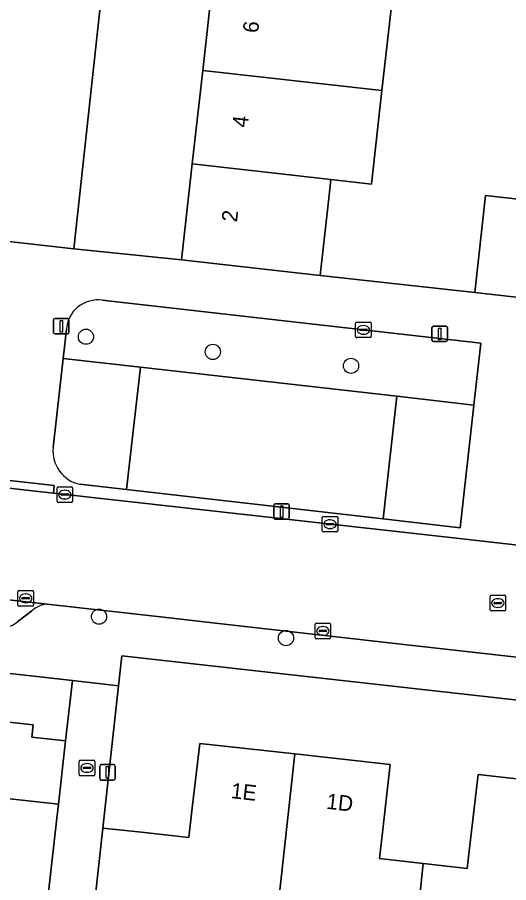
# Model space of a CAD drawing. Extents: x 162082 to 163401, y 388089 to 388636.
# Drawn here: x 162878.5 to 162910.1, y 388312.7 to 388368.3 of the extents above; entities that cross this region are included whole.
import ezdxf

# ---------------------------------------------------------------- set-up
doc = ezdxf.new("R2010")
doc.units = 0
for name, color, linetype in [('IMGEO_Boom', 7, 'Continuous'), ('IMGEO_Erf', 7, 'Continuous'), ('IMGEO_Groenvoorziening', 7, 'Continuous'), ('IMGEO_Kolk', 7, 'Continuous'), ('IMGEO_Lichtmast', 7, 'Continuous'), ('IMGEO_Muur', 7, 'Continuous'), ('IMGEO_Pand', 7, 'Continuous'), ('IMGEO_Pand_nummerreeks', 7, 'Continuous'), ('IMGEO_Parkeervlak_open', 7, 'Continuous'), ('IMGEO_Rijbaan_lokaal_open', 7, 'Continuous'), ('IMGEO_Rioolput', 7, 'Continuous'), ('IMGEO_Voetpad_open', 7, 'Continuous')]:
    doc.layers.add(name, color=color, linetype=linetype)

msp = doc.modelspace()

# ---------------------------------------------------------------- linework, layer by layer
at = {"layer": 'IMGEO_Boom'}
for centre in [(162882.884, 388347.77), (162891.045, 388346.791), (162899.93, 388345.899), (162883.725, 388329.762), (162895.748, 388328.386)]:
    msp.add_circle(centre, 0.489, dxfattribs=at)
at = {"layer": 'IMGEO_Erf'}
for points in [[(162885.887, 388388.094), (162882.103, 388353.418), (162889.026, 388352.708), (162889.717, 388358.88), (162890.391, 388364.901), (162891.065, 388370.923)], [(162902.587, 388369.632), (162901.913, 388363.61), (162901.239, 388357.589), (162898.633, 388357.881), (162898.498, 388356.678), (162897.942, 388351.709), (162907.892, 388350.612), (162908.579, 388356.845), (162912.564, 388356.407), (162914.215, 388369.801)], [(162873.336, 388323.497), (162879.499, 388322.807), (162879.41, 388322.012), (162881.575, 388321.77), (162882.015, 388325.663), (162868.576, 388327.156)], [(162936.982, 388321.452), (162936.117, 388321.549), (162885.195, 388327.249), (162884.982, 388325.32), (162883.969, 388316.16), (162886.447, 388315.894), (162889.495, 388315.567), (162889.697, 388317.27), (162890.211, 388321.615), (162896.323, 388320.93), (162902.442, 388320.245), (162901.945, 388315.874), (162901.754, 388314.199), (162904.571, 388313.878), (162907.407, 388313.555), (162907.599, 388315.242), (162908.096, 388319.615), (162914.202, 388318.92), (162920.322, 388318.223), (162919.824, 388313.864), (162919.63, 388312.164)], [(162879.636, 388304.63), (162881.014, 388316.806), (162881.114, 388317.7), (162876.019, 388318.271)]]:
    msp.add_lwpolyline(points, dxfattribs=at)
at = {"layer": 'IMGEO_Groenvoorziening'}
for points in [[(162881.633, 388348.237), (162881.421, 388346.373), (162886.389, 388345.809), (162902.866, 388343.939), (162907.834, 388343.376), (162908.277, 388347.351), (162883.932, 388350.114)], [(162882.497, 388338.28), (162885.495, 388337.937), (162886.389, 388345.809), (162881.421, 388346.373), (162880.77, 388340.639)]]:
    msp.add_lwpolyline(points, dxfattribs=at)
for points in [[(162885.495, 388337.937), (162901.986, 388336.052), (162902.866, 388343.939), (162886.389, 388345.809)], [(162901.986, 388336.052), (162906.954, 388335.484), (162907.834, 388343.376), (162902.866, 388343.939)]]:
    msp.add_lwpolyline(points, close=True, dxfattribs=at)
for centre, radius, start, end in [((162883.635, 388348.131), 2.005, 81.4898, 176.9695), ((162882.955, 388340.427), 2.196, 174.4672, 257.9477)]:
    msp.add_arc(centre, radius, start, end, dxfattribs=at)
at = {"layer": 'IMGEO_Kolk'}
for p, q in [((162900.225, 388347.783), (162900.225, 388348.635)), ((162900.3, 388348.709), (162901.152, 388348.709)), ((162901.226, 388348.635), (162901.226, 388347.783)), ((162900.484, 388348.203), (162900.484, 388348.215)), ((162900.922, 388348.166), (162900.524, 388348.166)), ((162900.527, 388348.252), (162900.925, 388348.252)), ((162900.713, 388348.489), (162900.738, 388348.489)), ((162900.968, 388348.215), (162900.968, 388348.203)), ((162901.152, 388347.709), (162900.3, 388347.709)), ((162900.736, 388347.929), (162900.711, 388347.929)), ((162881.023, 388337.188), (162881.023, 388338.04)), ((162881.098, 388338.114), (162881.95, 388338.114)), ((162882.024, 388338.04), (162882.024, 388337.188)), ((162881.282, 388337.608), (162881.282, 388337.62)), ((162881.72, 388337.571), (162881.322, 388337.571)), ((162881.325, 388337.657), (162881.723, 388337.657)), ((162881.511, 388337.894), (162881.536, 388337.894)), ((162881.766, 388337.62), (162881.766, 388337.608)), ((162881.95, 388337.114), (162881.098, 388337.114)), ((162881.534, 388337.334), (162881.509, 388337.334)), ((162898.08, 388335.285), (162898.08, 388336.137)), ((162898.155, 388336.211), (162899.007, 388336.211)), ((162898.568, 388335.991), (162898.593, 388335.991)), ((162899.081, 388336.137), (162899.081, 388335.285)), ((162898.339, 388335.705), (162898.339, 388335.717)), ((162898.777, 388335.668), (162898.379, 388335.668)), ((162898.382, 388335.754), (162898.78, 388335.754)), ((162898.591, 388335.431), (162898.566, 388335.431)), ((162898.823, 388335.717), (162898.823, 388335.705)), ((162899.007, 388335.211), (162898.155, 388335.211)), ((162878.511, 388330.519), (162878.511, 388331.371)), ((162878.586, 388331.445), (162879.438, 388331.445)), ((162879.512, 388331.371), (162879.512, 388330.519)), ((162878.77, 388330.939), (162878.77, 388330.951)), ((162879.208, 388330.902), (162878.81, 388330.902)), ((162878.813, 388330.988), (162879.211, 388330.988)), ((162878.999, 388331.225), (162879.024, 388331.225)), ((162879.254, 388330.951), (162879.254, 388330.939)), ((162879.438, 388330.445), (162878.586, 388330.445)), ((162879.022, 388330.665), (162878.997, 388330.665)), ((162897.616, 388328.421), (162897.616, 388329.273)), ((162897.691, 388329.347), (162898.543, 388329.347)), ((162898.617, 388329.273), (162898.617, 388328.421)), ((162897.875, 388328.841), (162897.875, 388328.853)), ((162898.313, 388328.804), (162897.915, 388328.804)), ((162897.918, 388328.89), (162898.316, 388328.89)), ((162898.104, 388329.127), (162898.129, 388329.127)), ((162898.359, 388328.853), (162898.359, 388328.841)), ((162898.543, 388328.347), (162897.691, 388328.347)), ((162898.127, 388328.567), (162898.102, 388328.567)), ((162882.451, 388319.605), (162882.451, 388320.457)), ((162882.526, 388320.531), (162883.378, 388320.531)), ((162882.939, 388320.311), (162882.964, 388320.311)), ((162883.452, 388320.457), (162883.452, 388319.605)), ((162882.71, 388320.025), (162882.71, 388320.037)), ((162883.148, 388319.988), (162882.75, 388319.988)), ((162882.753, 388320.074), (162883.151, 388320.074)), ((162882.962, 388319.751), (162882.937, 388319.751)), ((162883.194, 388320.037), (162883.194, 388320.025)), ((162883.378, 388319.531), (162882.526, 388319.531))]:
    msp.add_line(p, q, dxfattribs=at)
for points in [[(162900.225, 388347.783), (162900.225, 388348.635)], [(162900.3, 388348.709), (162901.152, 388348.709)], [(162901.226, 388348.635), (162901.226, 388347.783)], [(162901.152, 388347.709), (162900.3, 388347.709)], [(162881.023, 388337.188), (162881.023, 388338.04)], [(162881.098, 388338.114), (162881.95, 388338.114)], [(162882.024, 388338.04), (162882.024, 388337.188)], [(162881.95, 388337.114), (162881.098, 388337.114)], [(162898.08, 388335.285), (162898.08, 388336.137)], [(162898.155, 388336.211), (162899.007, 388336.211)], [(162899.081, 388336.137), (162899.081, 388335.285)], [(162899.007, 388335.211), (162898.155, 388335.211)], [(162878.511, 388330.519), (162878.511, 388331.371)], [(162878.586, 388331.445), (162879.438, 388331.445)], [(162879.512, 388331.371), (162879.512, 388330.519)], [(162879.438, 388330.445), (162878.586, 388330.445)], [(162897.616, 388328.421), (162897.616, 388329.273)], [(162897.691, 388329.347), (162898.543, 388329.347)], [(162898.617, 388329.273), (162898.617, 388328.421)], [(162898.543, 388328.347), (162897.691, 388328.347)], [(162882.451, 388319.605), (162882.451, 388320.457)], [(162882.526, 388320.531), (162883.378, 388320.531)], [(162883.452, 388320.457), (162883.452, 388319.605)], [(162883.378, 388319.531), (162882.526, 388319.531)]]:
    msp.add_lwpolyline(points, dxfattribs=at)
for centre, radius, start, end in [((162900.302, 388348.633), 0.0765, 91.552, 178.448), ((162900.302, 388348.633), 0.0765, 91.552, 178.448), ((162901.15, 388348.633), 0.0765, 1.552, 88.448), ((162901.15, 388348.633), 0.0765, 1.552, 88.448), ((162900.524, 388348.212), 0.0403, 85.8775, 175.7526), ((162900.521, 388348.202), 0.0366, 178.938, 274.7102), ((162900.925, 388348.209), 0.043, 264.8664, 352.4533), ((162900.929, 388348.214), 0.0386, 1.7309, 96.639), ((162900.302, 388347.785), 0.0765, 181.552, 268.448), ((162900.302, 388347.785), 0.0765, 181.552, 268.448), ((162901.15, 388347.785), 0.0765, 271.552, 358.448), ((162901.15, 388347.785), 0.0765, 271.552, 358.448), ((162881.1, 388338.038), 0.0765, 91.552, 178.448), ((162881.1, 388338.038), 0.0765, 91.552, 178.448), ((162881.948, 388338.038), 0.0765, 1.552, 88.448), ((162881.948, 388338.038), 0.0765, 1.552, 88.448), ((162881.322, 388337.617), 0.0403, 85.8775, 175.7526), ((162881.319, 388337.607), 0.0366, 178.938, 274.7102), ((162881.723, 388337.614), 0.043, 264.8664, 352.4533), ((162881.727, 388337.619), 0.0386, 1.7309, 96.639), ((162881.1, 388337.19), 0.0765, 181.552, 268.448), ((162881.1, 388337.19), 0.0765, 181.552, 268.448), ((162881.948, 388337.19), 0.0765, 271.552, 358.448), ((162881.948, 388337.19), 0.0765, 271.552, 358.448), ((162898.157, 388336.135), 0.0765, 91.552, 178.448), ((162898.157, 388336.135), 0.0765, 91.552, 178.448), ((162899.005, 388336.135), 0.0765, 1.552, 88.448), ((162899.005, 388336.135), 0.0765, 1.552, 88.448), ((162898.157, 388335.287), 0.0765, 181.552, 268.448), ((162898.157, 388335.287), 0.0765, 181.552, 268.448), ((162898.379, 388335.714), 0.0403, 85.8775, 175.7526), ((162898.376, 388335.704), 0.0366, 178.938, 274.7102), ((162898.78, 388335.711), 0.043, 264.8664, 352.4533), ((162898.784, 388335.716), 0.0386, 1.7309, 96.639), ((162899.005, 388335.287), 0.0765, 271.552, 358.448), ((162899.005, 388335.287), 0.0765, 271.552, 358.448), ((162878.588, 388331.369), 0.0765, 91.552, 178.448), ((162878.588, 388331.369), 0.0765, 91.552, 178.448), ((162879.436, 388331.369), 0.0765, 1.552, 88.448), ((162879.436, 388331.369), 0.0765, 1.552, 88.448), ((162878.81, 388330.948), 0.0403, 85.8775, 175.7526), ((162878.807, 388330.938), 0.0366, 178.938, 274.7102), ((162879.211, 388330.945), 0.043, 264.8664, 352.4533), ((162879.215, 388330.95), 0.0386, 1.7309, 96.639), ((162878.588, 388330.521), 0.0765, 181.552, 268.448), ((162878.588, 388330.521), 0.0765, 181.552, 268.448), ((162879.436, 388330.521), 0.0765, 271.552, 358.448), ((162879.436, 388330.521), 0.0765, 271.552, 358.448), ((162897.693, 388329.271), 0.0765, 91.552, 178.448), ((162897.693, 388329.271), 0.0765, 91.552, 178.448), ((162898.541, 388329.271), 0.0765, 1.552, 88.448), ((162898.541, 388329.271), 0.0765, 1.552, 88.448), ((162897.915, 388328.85), 0.0403, 85.8775, 175.7526), ((162897.912, 388328.84), 0.0366, 178.938, 274.7102), ((162898.316, 388328.847), 0.043, 264.8664, 352.4533), ((162898.32, 388328.852), 0.0386, 1.7309, 96.639), ((162897.693, 388328.423), 0.0765, 181.552, 268.448), ((162897.693, 388328.423), 0.0765, 181.552, 268.448), ((162898.541, 388328.423), 0.0765, 271.552, 358.448), ((162898.541, 388328.423), 0.0765, 271.552, 358.448), ((162882.528, 388320.455), 0.0765, 91.552, 178.448), ((162882.528, 388320.455), 0.0765, 91.552, 178.448), ((162883.376, 388320.455), 0.0765, 1.552, 88.448), ((162883.376, 388320.455), 0.0765, 1.552, 88.448), ((162882.75, 388320.034), 0.0403, 85.8775, 175.7526), ((162882.747, 388320.024), 0.0366, 178.938, 274.7102), ((162883.151, 388320.031), 0.043, 264.8664, 352.4533), ((162883.155, 388320.036), 0.0386, 1.7309, 96.639), ((162882.528, 388319.607), 0.0765, 181.552, 268.448), ((162882.528, 388319.607), 0.0765, 181.552, 268.448), ((162883.376, 388319.607), 0.0765, 271.552, 358.448), ((162883.376, 388319.607), 0.0765, 271.552, 358.448)]:
    msp.add_arc(centre, radius, start, end, dxfattribs=at)
for centre, major_axis, ratio, start_param, end_param in [((162900.712, 388348.209), (-0.387, 0.002), 0.722429, 4.712389, 7.853982), ((162900.737, 388348.209), (-0.39, 0.002), 0.717154, 1.570796, 4.712389), ((162881.51, 388337.614), (-0.387, 0.002), 0.722429, 4.712389, 7.853982), ((162881.535, 388337.614), (-0.39, 0.002), 0.717154, 1.570796, 4.712389), ((162898.567, 388335.711), (-0.387, 0.002), 0.722429, 4.712389, 7.853982), ((162898.592, 388335.711), (-0.39, 0.002), 0.717154, 1.570796, 4.712389), ((162878.998, 388330.945), (-0.387, 0.002), 0.722429, 4.712389, 7.853982), ((162879.023, 388330.945), (-0.39, 0.002), 0.717154, 1.570796, 4.712389), ((162898.103, 388328.847), (-0.387, 0.002), 0.722429, 4.712389, 7.853982), ((162898.128, 388328.847), (-0.39, 0.002), 0.717154, 1.570796, 4.712389), ((162882.938, 388320.031), (-0.387, 0.002), 0.722429, 4.712389, 7.853982), ((162882.963, 388320.031), (-0.39, 0.002), 0.717154, 1.570796, 4.712389)]:
    msp.add_ellipse(centre, major_axis=major_axis, ratio=ratio, start_param=start_param, end_param=end_param, dxfattribs=at)
at = {"layer": 'IMGEO_Lichtmast'}
for p, q in [((162880.8, 388348.048), (162880.8, 388348.848)), ((162880.8, 388348.848), (162880.8, 388348.048)), ((162880.9, 388348.948), (162881.69, 388348.948)), ((162881.69, 388348.948), (162880.9, 388348.948)), ((162881.79, 388348.848), (162881.79, 388348.048)), ((162881.79, 388348.048), (162881.79, 388348.848)), ((162905.134, 388347.555), (162905.134, 388348.355)), ((162905.134, 388348.355), (162905.134, 388347.555)), ((162905.234, 388348.455), (162906.024, 388348.455)), ((162906.024, 388348.455), (162905.234, 388348.455)), ((162906.124, 388348.355), (162906.124, 388347.555)), ((162906.124, 388347.555), (162906.124, 388348.355)), ((162881.69, 388347.948), (162880.9, 388347.948)), ((162880.9, 388347.948), (162881.69, 388347.948)), ((162906.024, 388347.455), (162905.234, 388347.455)), ((162905.234, 388347.455), (162906.024, 388347.455)), ((162894.968, 388336.126), (162894.968, 388336.926)), ((162894.968, 388336.926), (162894.968, 388336.126)), ((162895.068, 388337.026), (162895.858, 388337.026)), ((162895.858, 388337.026), (162895.068, 388337.026)), ((162895.958, 388336.926), (162895.958, 388336.126)), ((162895.958, 388336.126), (162895.958, 388336.926)), ((162895.858, 388336.026), (162895.068, 388336.026)), ((162895.068, 388336.026), (162895.858, 388336.026)), ((162883.872, 388320.256), (162884.662, 388320.256)), ((162884.662, 388320.256), (162883.872, 388320.256)), ((162883.772, 388319.356), (162883.772, 388320.156)), ((162883.772, 388320.156), (162883.772, 388319.356)), ((162884.762, 388320.156), (162884.762, 388319.356)), ((162884.762, 388319.356), (162884.762, 388320.156)), ((162884.662, 388319.256), (162883.872, 388319.256)), ((162883.872, 388319.256), (162884.662, 388319.256))]:
    msp.add_line(p, q, dxfattribs=at)
for points in [[(162881.22, 388348.823), (162881.37, 388348.823), (162881.37, 388348.073), (162881.22, 388348.073), (162881.22, 388348.823)], [(162905.554, 388348.33), (162905.704, 388348.33), (162905.704, 388347.58), (162905.554, 388347.58), (162905.554, 388348.33)], [(162895.388, 388336.901), (162895.538, 388336.901), (162895.538, 388336.151), (162895.388, 388336.151), (162895.388, 388336.901)], [(162884.192, 388320.131), (162884.342, 388320.131), (162884.342, 388319.381), (162884.192, 388319.381), (162884.192, 388320.131)]]:
    msp.add_lwpolyline(points, dxfattribs=at)
for centre, start, end in [((162880.9, 388348.848), 90, 180), ((162880.9, 388348.848), 90, 180), ((162881.69, 388348.848), 0, 90), ((162881.69, 388348.848), 360, 90), ((162905.234, 388348.355), 90, 180), ((162905.234, 388348.355), 90, 180), ((162906.024, 388348.355), 0, 90), ((162906.024, 388348.355), 360, 90), ((162880.9, 388348.048), 180, 270), ((162880.9, 388348.048), 180, 270), ((162881.69, 388348.048), 270, 0), ((162881.69, 388348.048), 270, 0), ((162905.234, 388347.555), 180, 270), ((162905.234, 388347.555), 180, 270), ((162906.024, 388347.555), 270, 0), ((162906.024, 388347.555), 270, 0), ((162895.068, 388336.926), 90, 180), ((162895.068, 388336.926), 90, 180), ((162895.858, 388336.926), 0, 90), ((162895.858, 388336.926), 360, 90), ((162895.068, 388336.126), 180, 270), ((162895.068, 388336.126), 180, 270), ((162895.858, 388336.126), 270, 0), ((162895.858, 388336.126), 270, 0), ((162883.872, 388320.156), 90, 180), ((162883.872, 388320.156), 90, 180), ((162884.662, 388320.156), 0, 90), ((162884.662, 388320.156), 360, 90), ((162883.872, 388319.356), 180, 270), ((162883.872, 388319.356), 180, 270), ((162884.662, 388319.356), 270, 0), ((162884.662, 388319.356), 270, 0)]:
    msp.add_arc(centre, 0.1, start, end, dxfattribs=at)
at = {"layer": 'IMGEO_Muur'}
for points in [[(162907.892, 388350.612), (162897.942, 388351.709)], [(162881.014, 388316.806), (162879.636, 388304.63)]]:
    msp.add_lwpolyline(points, dxfattribs=at)
at = {"layer": 'IMGEO_Pand'}
for points in [[(162890.391, 388364.901), (162901.913, 388363.61), (162902.587, 388369.632), (162899.981, 388369.924), (162891.065, 388370.923)], [(162890.391, 388364.901), (162889.717, 388358.88), (162898.633, 388357.881), (162901.239, 388357.589), (162901.913, 388363.61)], [(162898.633, 388357.881), (162889.717, 388358.88), (162889.026, 388352.708), (162897.942, 388351.709), (162898.498, 388356.678)], [(162911.877, 388350.172), (162912.564, 388356.407), (162908.579, 388356.845), (162907.892, 388350.612)], [(162869.223, 388313.359), (162875.392, 388312.668), (162876.019, 388318.271), (162881.114, 388317.7), (162881.575, 388321.77), (162879.41, 388322.012), (162879.499, 388322.807), (162873.336, 388323.497), (162872.805, 388318.759), (162869.868, 388319.088)], [(162894.755, 388306.71), (162896.323, 388320.93), (162890.211, 388321.615), (162889.697, 388317.27), (162889.495, 388315.567), (162886.447, 388315.894), (162883.969, 388316.16), (162883.192, 388309.144), (162882.593, 388303.237), (162885.723, 388302.89), (162888.007, 388306.445), (162891.46, 388306.061), (162891.576, 388307.063)], [(162904.571, 388313.878), (162901.754, 388314.199), (162901.945, 388315.874), (162902.442, 388320.245), (162896.323, 388320.93), (162894.755, 388306.71), (162898.257, 388306.321), (162898.368, 388307.41), (162903.836, 388306.803)], [(162904.571, 388313.878), (162903.836, 388306.803), (162909.255, 388306.202), (162909.677, 388310.134), (162913.18, 388309.749), (162914.202, 388318.92), (162908.096, 388319.615), (162907.599, 388315.242), (162907.407, 388313.555)]]:
    msp.add_lwpolyline(points, close=True, dxfattribs=at)
at = {"layer": 'IMGEO_Parkeervlak_open'}
for points in [[(162880.401, 388330.569), (162802.146, 388339.314)], [(162878.507, 388329.455), (162879.411, 388330.141)]]:
    msp.add_lwpolyline(points, dxfattribs=at)
for centre, radius, start, end in [((162880.483, 388329.02), 1.551, 93.0334, 133.7265), ((162877.295, 388330.889), 1.878, 259.474, 310.2053)]:
    msp.add_arc(centre, radius, start, end, dxfattribs=at)
at = {"layer": 'IMGEO_Rijbaan_lokaal_open'}
msp.add_lwpolyline([(162888.58, 388412.169), (162879.563, 388413.177), (162873.15, 388354.422), (162882.103, 388353.418), (162885.887, 388388.094), (162886.264, 388391.474)], close=True, dxfattribs=at)
msp.add_lwpolyline([(162802.146, 388339.314), (162880.401, 388330.569), (162887.687, 388329.747), (162891.415, 388329.326), (162902.379, 388328.088), (162909.812, 388327.25), (162920.38, 388326.057), (162927.727, 388325.228), (162937.375, 388324.139), (162937.647, 388331.155), (162910.107, 388334.435), (162906.331, 388334.857), (162880.788, 388337.712), (162871.19, 388338.785)], dxfattribs=at)
at = {"layer": 'IMGEO_Rioolput'}
for p, q in [((162908.872, 388330.213), (162908.872, 388331.065)), ((162908.947, 388331.139), (162909.799, 388331.139)), ((162909.36, 388330.919), (162909.385, 388330.919)), ((162909.873, 388331.065), (162909.873, 388330.213)), ((162909.131, 388330.633), (162909.131, 388330.645)), ((162909.569, 388330.596), (162909.171, 388330.596)), ((162909.174, 388330.682), (162909.572, 388330.682)), ((162909.383, 388330.359), (162909.358, 388330.359)), ((162909.615, 388330.645), (162909.615, 388330.633)), ((162909.799, 388330.139), (162908.947, 388330.139))]:
    msp.add_line(p, q, dxfattribs=at)
for points in [[(162908.872, 388330.213), (162908.872, 388331.065)], [(162908.947, 388331.139), (162909.799, 388331.139)], [(162909.873, 388331.065), (162909.873, 388330.213)], [(162909.799, 388330.139), (162908.947, 388330.139)]]:
    msp.add_lwpolyline(points, dxfattribs=at)
for centre, radius, start, end in [((162908.949, 388331.063), 0.0765, 91.552, 178.448), ((162908.949, 388331.063), 0.0765, 91.552, 178.448), ((162909.797, 388331.063), 0.0765, 1.552, 88.448), ((162909.797, 388331.063), 0.0765, 1.552, 88.448), ((162909.171, 388330.642), 0.0403, 85.8775, 175.7526), ((162909.168, 388330.632), 0.0366, 178.938, 274.7102), ((162909.572, 388330.639), 0.043, 264.8664, 352.4533), ((162909.576, 388330.644), 0.0386, 1.7309, 96.639), ((162908.949, 388330.215), 0.0765, 181.552, 268.448), ((162908.949, 388330.215), 0.0765, 181.552, 268.448), ((162909.797, 388330.215), 0.0765, 271.552, 358.448), ((162909.797, 388330.215), 0.0765, 271.552, 358.448)]:
    msp.add_arc(centre, radius, start, end, dxfattribs=at)
for centre, major_axis, ratio, start_param, end_param in [((162909.359, 388330.639), (-0.387, 0.002), 0.722429, 4.712389, 7.853982), ((162909.384, 388330.639), (-0.39, 0.002), 0.717154, 1.570796, 4.712389)]:
    msp.add_ellipse(centre, major_axis=major_axis, ratio=ratio, start_param=start_param, end_param=end_param, dxfattribs=at)
at = {"layer": 'IMGEO_Voetpad_open'}
for points in [[(162938.677, 388341.882), (162939.248, 388347.057), (162936.278, 388347.432), (162927.507, 388348.418), (162924.961, 388348.704), (162915.931, 388349.732), (162913.387, 388350.012), (162911.877, 388350.172), (162907.892, 388350.612), (162897.942, 388351.709), (162889.026, 388352.708), (162882.103, 388353.418), (162873.15, 388354.422), (162872.693, 388349.366), (162872.484, 388347.361), (162871.88, 388341.578), (162871.635, 388339.233), (162880.84, 388338.193), (162880.788, 388337.712), (162906.331, 388334.857), (162910.107, 388334.435), (162937.647, 388331.155), (162937.826, 388333.98)], [(162883.932, 388350.114), (162908.277, 388347.351), (162907.834, 388343.376), (162906.954, 388335.484), (162901.986, 388336.052), (162885.495, 388337.937), (162882.497, 388338.28)], [(162881.421, 388346.373), (162881.633, 388348.237)], [(162880.77, 388340.639), (162881.421, 388346.373)], [(162736.116, 388341.858), (162740.3, 388341.413), (162793.443, 388335.388), (162796.49, 388335.147), (162868.576, 388327.156), (162882.015, 388325.663), (162884.982, 388325.32), (162885.195, 388327.249), (162936.117, 388321.549), (162936.982, 388321.452), (162943.064, 388320.814)], [(162891.415, 388329.326), (162887.687, 388329.747), (162880.401, 388330.569)], [(162879.411, 388330.141), (162878.507, 388329.455)], [(162937.375, 388324.139), (162927.727, 388325.228), (162920.38, 388326.057), (162909.812, 388327.25), (162902.379, 388328.088), (162891.415, 388329.326)]]:
    msp.add_lwpolyline(points, dxfattribs=at)
for points in [[(162871.635, 388339.233), (162871.243, 388339.277), (162871.19, 388338.785), (162880.788, 388337.712), (162880.84, 388338.193)], [(162908.073, 388271.01), (162910.054, 388288.891), (162907.123, 388289.226), (162886.23, 388291.615), (162886.758, 388296.567), (162881.865, 388297.138), (162882.593, 388303.237), (162883.192, 388309.144), (162883.969, 388316.16), (162884.982, 388325.32), (162882.015, 388325.663), (162881.575, 388321.77), (162881.114, 388317.7), (162881.014, 388316.806), (162879.636, 388304.63), (162879.611, 388304.409), (162879.495, 388303.388), (162878.843, 388297.493), (162877.935, 388289.522), (162879.495, 388289.345), (162906.732, 388286.253), (162904.351, 388264.947), (162907.36, 388264.58)]]:
    msp.add_lwpolyline(points, close=True, dxfattribs=at)
for centre, radius, start, end in [((162883.635, 388348.131), 2.005, 81.4898, 176.9695), ((162882.955, 388340.427), 2.196, 174.4672, 257.9477), ((162880.483, 388329.02), 1.551, 93.0334, 133.7265), ((162877.295, 388330.889), 1.878, 259.474, 310.2053)]:
    msp.add_arc(centre, radius, start, end, dxfattribs=at)

# ---------------------------------------------------------------- texts
at = {"layer": 'IMGEO_Pand_nummerreeks'}
for s, rotation, p in [('6', 83.612, (162893.957, 388367.272)), ('4', 83.612, (162893.276, 388361.191)), ('2', 83.612, (162892.595, 388355.108)), ('1E', 353.6089, (162892.171, 388318.095)), ('1D', 353.6089, (162898.309, 388317.408))]:
    msp.add_text(s, height=1, rotation=rotation, dxfattribs=at).set_placement(p)

doc.saveas('drawing.dxf')
